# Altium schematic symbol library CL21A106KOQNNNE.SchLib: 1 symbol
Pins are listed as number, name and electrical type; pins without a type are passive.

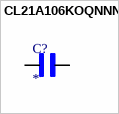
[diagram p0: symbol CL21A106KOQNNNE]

## CL21A106KOQNNNE
designator C?
MP: CL21A106KOQNNNE
footprint CAPC2012X140N
pins: 1, 2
